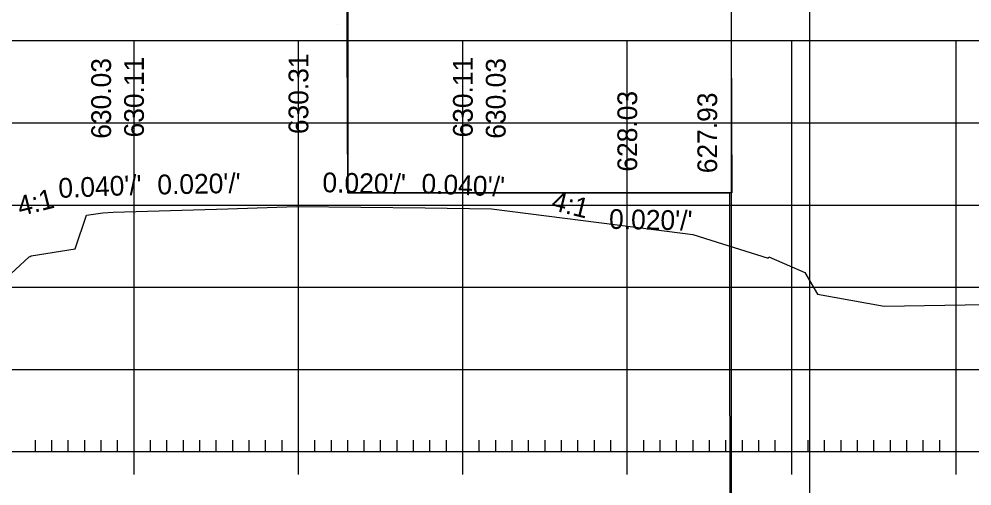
# Model space of a CAD drawing. Extents: x 1381471 to 1382703, y 370300 to 371487.
# Drawn here: x 1382119.6 to 1382177.6, y 370696.7 to 370725.1 of the extents above; entities that cross this region are included whole.
import ezdxf

# ---------------------------------------------------------------- set-up
doc = ezdxf.new("R2010")
doc.units = 0
for name, color, linetype in [('Level 26', 7, 'Continuous'), ('Level 45', 7, 'Continuous'), ('Level 6', 7, 'Continuous')]:
    doc.layers.add(name, color=color, linetype=linetype)

msp = doc.modelspace()

# ---------------------------------------------------------------- linework, layer by layer
at = {"layer": 'Level 26'}
msp.add_line((1382138.986, 370724.735), (1382138.986, 370724.735), dxfattribs=at)
for points in [[(1381834.365, 370760.966), (1382167.705, 370760.966), (1382167.705, 370547.628), (1381834.365, 370547.628)], [(1382080.692, 370757.071), (1382100.312, 370757.071), (1382100.312, 370747.191), (1382116.424, 370747.191), (1382139.624, 370747.191), (1382139.624, 370714.521), (1382162.831, 370714.521), (1382162.952, 370551.611), (1381846.772, 370551.611), (1381846.772, 370757.071)], [(1382139.484, 370747.191), (1382162.831, 370747.191), (1382162.972, 370714.521), (1382139.624, 370714.521)]]:
    msp.add_lwpolyline(points, close=True, dxfattribs=at)
at = {"layer": 'Level 45'}
for p, q in [((1381996.613, 370723.782), (1382276.613, 370723.782)), ((1382126.613, 370698.782), (1382126.613, 370723.782)), ((1382136.613, 370698.782), (1382136.613, 370723.782)), ((1382146.613, 370698.782), (1382146.613, 370723.782)), ((1382156.613, 370698.782), (1382156.613, 370723.782)), ((1382166.613, 370698.782), (1382166.613, 370723.782)), ((1382176.613, 370698.782), (1382176.613, 370723.782)), ((1381996.613, 370718.782), (1382276.613, 370718.782)), ((1381996.613, 370713.782), (1382276.613, 370713.782)), ((1381996.613, 370708.782), (1382276.613, 370708.782)), ((1381996.613, 370703.782), (1382276.613, 370703.782)), ((1382126.613, 370697.382), (1382126.613, 370700.182)), ((1382136.613, 370697.382), (1382136.613, 370700.182)), ((1382146.613, 370697.382), (1382146.613, 370700.182)), ((1382156.613, 370697.382), (1382156.613, 370700.182)), ((1382166.613, 370697.382), (1382166.613, 370700.182)), ((1382176.613, 370697.382), (1382176.613, 370700.182)), ((1382120.613, 370698.782), (1382120.613, 370699.482)), ((1382121.613, 370698.782), (1382121.613, 370699.482)), ((1382122.613, 370698.782), (1382122.613, 370699.482)), ((1382123.613, 370698.782), (1382123.613, 370699.482)), ((1382124.613, 370698.782), (1382124.613, 370699.482)), ((1382125.613, 370698.782), (1382125.613, 370699.482)), ((1382127.613, 370698.782), (1382127.613, 370699.482)), ((1382128.613, 370698.782), (1382128.613, 370699.482)), ((1382129.613, 370698.782), (1382129.613, 370699.482)), ((1382130.613, 370698.782), (1382130.613, 370699.482)), ((1382131.613, 370698.782), (1382131.613, 370699.482)), ((1382132.613, 370698.782), (1382132.613, 370699.482)), ((1382133.613, 370698.782), (1382133.613, 370699.482)), ((1382134.613, 370698.782), (1382134.613, 370699.482)), ((1382135.613, 370698.782), (1382135.613, 370699.482)), ((1382137.613, 370698.782), (1382137.613, 370699.482)), ((1382138.613, 370698.782), (1382138.613, 370699.482)), ((1382139.613, 370698.782), (1382139.613, 370699.482)), ((1382140.613, 370698.782), (1382140.613, 370699.482)), ((1382141.613, 370698.782), (1382141.613, 370699.482)), ((1382142.613, 370698.782), (1382142.613, 370699.482)), ((1382143.613, 370698.782), (1382143.613, 370699.482)), ((1382144.613, 370698.782), (1382144.613, 370699.482)), ((1382145.613, 370698.782), (1382145.613, 370699.482)), ((1382147.613, 370698.782), (1382147.613, 370699.482)), ((1382148.613, 370698.782), (1382148.613, 370699.482)), ((1382149.613, 370698.782), (1382149.613, 370699.482)), ((1382150.613, 370698.782), (1382150.613, 370699.482)), ((1382151.613, 370698.782), (1382151.613, 370699.482)), ((1382152.613, 370698.782), (1382152.613, 370699.482)), ((1382153.613, 370698.782), (1382153.613, 370699.482)), ((1382154.613, 370698.782), (1382154.613, 370699.482)), ((1382155.613, 370698.782), (1382155.613, 370699.482)), ((1382157.613, 370698.782), (1382157.613, 370699.482)), ((1382158.613, 370698.782), (1382158.613, 370699.482)), ((1382159.613, 370698.782), (1382159.613, 370699.482)), ((1382160.613, 370698.782), (1382160.613, 370699.482)), ((1382161.613, 370698.782), (1382161.613, 370699.482)), ((1382162.613, 370698.782), (1382162.613, 370699.482)), ((1382163.613, 370698.782), (1382163.613, 370699.482)), ((1382164.613, 370698.782), (1382164.613, 370699.482)), ((1382165.613, 370698.782), (1382165.613, 370699.482)), ((1382167.613, 370698.782), (1382167.613, 370699.482)), ((1382168.613, 370698.782), (1382168.613, 370699.482)), ((1382169.613, 370698.782), (1382169.613, 370699.482)), ((1382170.613, 370698.782), (1382170.613, 370699.482)), ((1382171.613, 370698.782), (1382171.613, 370699.482)), ((1382172.613, 370698.782), (1382172.613, 370699.482)), ((1382173.613, 370698.782), (1382173.613, 370699.482)), ((1382174.613, 370698.782), (1382174.613, 370699.482)), ((1382175.613, 370698.782), (1382175.613, 370699.482)), ((1381996.613, 370698.782), (1382276.613, 370698.782)), ((1381996.613, 370698.782), (1382276.613, 370698.782))]:
    msp.add_line(p, q, dxfattribs=at)
msp.add_lwpolyline([(1382060.367, 370707.751), (1382100.468, 370709.331), (1382118.576, 370709.098), (1382120.238, 370710.623), (1382120.286, 370710.659), (1382120.347, 370710.689), (1382123.039, 370711.114), (1382123.727, 370713.168), (1382124.72, 370713.303), (1382125.344, 370713.346), (1382132.324, 370713.557), (1382136.499, 370713.689), (1382144.315, 370713.601), (1382148.355, 370713.548), (1382158.234, 370712.298), (1382160.603, 370711.997), (1382161.689, 370711.648), (1382165.177, 370710.545), (1382165.231, 370710.632), (1382167.416, 370709.684), (1382168.189, 370708.364), (1382172.246, 370707.627), (1382183.305, 370707.806)], dxfattribs=at)
at = {"layer": 'Level 6'}
msp.add_line((1382162.952, 370551.611), (1382162.952, 370757.071), dxfattribs=at)

# ---------------------------------------------------------------- texts
at = {"layer": 'Level 45'}
for s, rotation, p in [('630.31', 90, (1382137.213, 370718.092)), ('630.03', 90, (1382125.213, 370717.812)), ('630.11', 90, (1382127.213, 370717.892)), ('630.11', 90, (1382147.213, 370717.892)), ('630.03', 90, (1382149.213, 370717.812)), ('628.03', 90, (1382157.213, 370715.812)), ('627.93', 90, (1382162.079, 370715.715)), ("0.020'/'", 1.14576, (1382128.042, 370714.421)), ("0.020'/'", 358.85424, (1382138.062, 370714.563)), ("0.040'/'", 2.29061, (1382122.034, 370714.21)), ("0.040'/'", 357.70939, (1382144.074, 370714.494)), ('4:1', 14.03624, (1382119.685, 370713.096)), ('4:1', 345.96376, (1382151.928, 370713.499)), ("0.020'/'", 358.85424, (1382155.495, 370712.335))]:
    msp.add_text(s, height=1.2, rotation=rotation, dxfattribs=at).set_placement(p)

doc.saveas('drawing.dxf')
